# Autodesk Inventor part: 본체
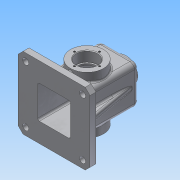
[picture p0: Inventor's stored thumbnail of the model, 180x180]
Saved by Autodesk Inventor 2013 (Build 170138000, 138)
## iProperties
Created: 2018-10
Part Number: 본체
Material: 알루미늄 6061
Document SubType Name: Modeling
Designer: Administrator
Density: 2.71 g/cm^3
Mass: 797.272 g
Surface Area: 899.908 cm^2
Volume: 294.196 cm^3
Author: Administrator
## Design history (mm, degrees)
sketch "스케치1"
  geometry: L1 (32.5, -32.5)-(-32.5, -32.5); L2 (-32.5, -32.5)-(-32.5, 32.5); L3 (-32.5, 32.5)-(32.5, 32.5); L4 (32.5, 32.5)-(32.5, -32.5); L5 (32.5, -32.5)-(-32.5, 32.5); L6 (-32.5, -32.5)-(32.5, 32.5); 1 further point
  constraints: 12 end point, 2 midpoint, 2 parallel, 1 horizontal, 1 perpendicular
  dimensions: "d0" = 65 distance of L2.end L3.end; "d1" = 65 distance of L1.end L2.end
extrude "돌출1" new body sketch "스케치1" stored distance "d2" = 110; taper "d3" = 0 deg
sketch "스케치2"
  geometry: L1 (27.5, 27.5)-(-27.5, 27.5); L2 (-27.5, 27.5)-(-27.5, -27.5); L3 (-27.5, -27.5)-(27.5, -27.5); L4 (27.5, -27.5)-(27.5, 27.5); L5 (27.5, 27.5)-(-27.5, -27.5); L6 (-27.5, 27.5)-(27.5, -27.5); 1 further point
  constraints: 12 end point, 2 midpoint, 2 parallel, 1 horizontal, 1 perpendicular
  dimensions: "d4" = 55 distance of L1.start L1.end; "d6" = 55 distance of L3.end L1.start
extrude "돌출2" cut sketch "스케치2" distance "d7" = 105; taper "d8" = 0 deg
sketch "스케치3"
  geometry: L1 (-32.5, -32.5)-(32.5, -32.5) reference; L2 (32.5, -32.5)-(32.5, 32.5) reference; L3 (32.5, 32.5)-(-32.5, 32.5) reference; L4 (-32.5, 32.5)-(-32.5, -32.5) reference; L5 (60, -60)-(-60, -60); L6 (-60, -60)-(-60, 60); L7 (-60, 60)-(60, 60); L8 (60, 60)-(60, -60); L9 (60, -60)-(-60, 60); L10 (-60, -60)-(60, 60); 3 further points
  constraints: 12 end point, 3 midpoint, 2 parallel, 1 coincident, 1 horizontal, 1 perpendicular
  dimensions: "d9" = 120 distance of L6.end L7.end; "d10" = 120 distance of L5.end L6.end
extrude "돌출3" join sketch "스케치3" distance "d11" = 10; taper "d12" = 0 deg
chamfer "모따기1" distance "d13" = 8; stored, may be unused: second distance "d14" = 2, angle "d15" = 45 deg
sketch "스케치4"
  geometry: 5 further points
  constraints: 2 horizontal alignment, 2 vertical alignment
  dimensions: "d16" = 95 distance of point (47.5, 47.5) point (-47.5, 47.5); "d18" = 95 distance of point (-47.5, -47.5) point (-47.5, 47.5); "d19" = 47.5 horizontal distance of point (0, 0) point (-47.5, -47.5); "d20" = 47.5 horizontal distance of point (0, 0) point (-47.5, 47.5)
hole "구멍1" sketch "스케치4" at (-47.5, 47.5), (47.5, 47.5), (47.5, -47.5), (-47.5, -47.5) diameter "d21" = 10; stored, may be unused: countersink angle "d25" = 90 deg, drill point angle "d27" = 118 deg; dims "d22" = 6, "d23" = 4, "d24" = 2, "d26" = 8
fillet "모깎기1" dims "d28" = 3
fillet "모깎기2" dims "d29" = 3
fillet "모깎기3" dims "d30" = 8
fillet "모깎기4" dims "d31" = 8
sketch "스케치5"
  geometry: C1 r 27.5 at (24.5, 45); 1 further point
  constraints: 1 centre point, 1 coincident
  dimensions: "d32" = 55 diameter of C1
extrude "돌출4" join sketch "스케치5" distance "d33" = 15; taper "d34" = 0 deg
sketch "스케치6"
  geometry: C1 r 27.5 at (0, 0) reference; 1 further point
  constraints: 1 vertical alignment
  dimensions: "d35" = 21 distance of C1.centre point (0, 21)
hole "구멍2" sketch "스케치6" at (0, 21) diameter "d36" = 3.242; stored, may be unused: countersink angle "d40" = 90 deg, drill point angle "d42" = 118 deg; dims "d37" = 8, "d38" = 4, "d39" = 2, "d41" = 10
hole "구멍3" diameter "d48" = 30; stored, may be unused: countersink angle "d52" = 90 deg, drill point angle "d54" = 0 deg; dims "d46" = 10, "d47" = 10, "d49" = 8, "d50" = 35, "d51" = 17, "d53" = 10
chamfer "모따기2" distance "d55" = 1; stored, may be unused: second distance "d56" = 2, angle "d57" = 45 deg
fillet "모깎기5" dims "d58" = 3
node "작업 평면1"
sketch "스케치8"
  geometry: 1 further point
sketch "스케치9"
  geometry: C1 r 20 at (0, 0); 1 further point
  constraints: 1 centre point, 1 coincident
  dimensions: "d60" = 40 diameter of C1
extrude "돌출5" join sketch "스케치9" stored distance "d61" = 15; taper "d62" = 7 deg
hole "구멍4" sketch "스케치8" diameter "d63" = 22.835; stored, may be unused: countersink angle "d67" = 90 deg, drill point angle "d69" = 0 deg; dims "d64" = 8, "d65" = 35, "d66" = 17, "d68" = 10
fillet "모깎기6" dims "d70" = 0.3
fillet "모깎기7" dims "d71" = 0.3
sketch "스케치10"
  geometry: L1 (-33, 42.5)-(-42, 42.5); L2 (47, 27.5)-(-55, 27.5) reference; 1 further point
  constraints: 2 end point, 1 horizontal
  dimensions: "d72" = 15 distance between parallel lines of L2 L1
feature "리브1" sketch "스케치10" dims "d73" = 1, "d74" = 6, "d75" = 0, "d76" = 0, "d77" = 1, "d78" = 1
fillet "모깎기8" dims "d79" = 3
fillet "모깎기9" dims "d80" = 3
sketch "스케치11"
  geometry: L1 (-48, -45)-(-43.063, -17); L2 (-60, -55)-(-60, -45) reference; L3 (-52.5, -45)-(-42.5, -45) reference; 1 further point
  constraints: 2 end point, 1 point on line
  dimensions: "d81" = 10 deg angle of L2 L1; "d82" = 12 distance from line of L2 L1.start
feature "리브2" sketch "스케치11" dims "d83" = 1, "d84" = 10, "d85" = 0, "d86" = 0, "d87" = 1, "d88" = 1
fillet "모깎기10" dims "d89" = 3
fillet "모깎기11" dims "d90" = 3
fillet "모깎기12" dims "d91" = 1
sketch "스케치12"
  geometry: L1 (4.5, 18)-(44.5, 18) reference; L2 (-8, 0)-(-8, -91) reference; 1 further point
  constraints: 1 other
  dimensions: "d92" = 26 distance from line of L1 point (24.5, -8); "d93" = 32.5 distance from line of L2 point (24.5, -8)
feature "엠보싱1" sketch "스케치12" dims "d94" = 0.5, "d95" = 0
fillet "모깎기13" dims "d96" = 3
node "솔리드1"
pattern_circular "원형 패턴1" dims angle "d44" = 360 deg
mirror "대칭1"
mirror "대칭2"
mirror "대칭3"
